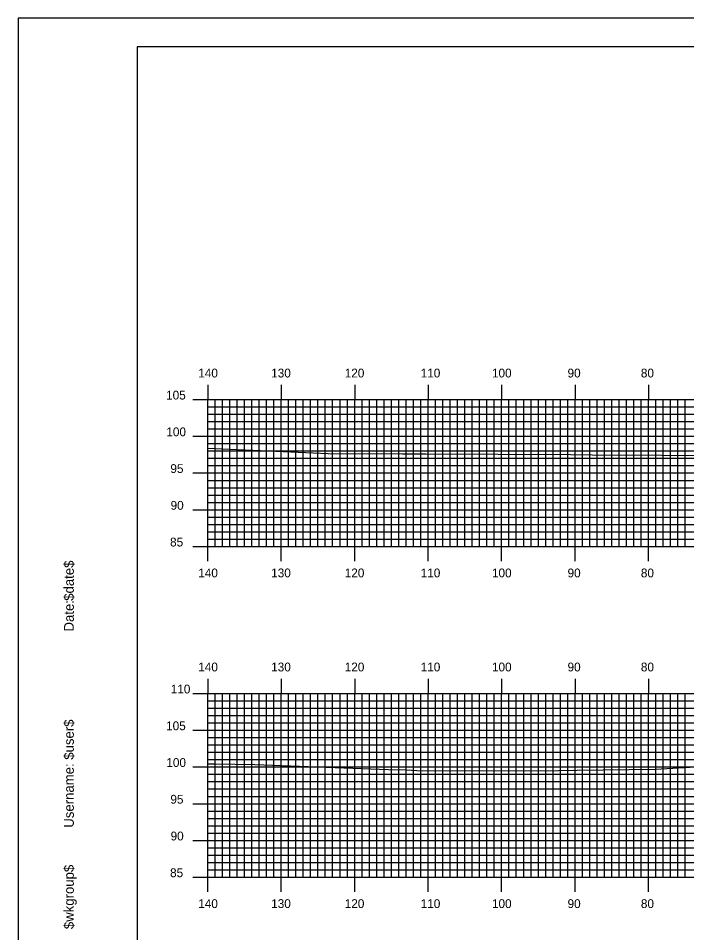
# Model space of a CAD drawing. Extents: x 1775170 to 1775514, y 442591 to 442811.
# Drawn here: x 1775170.4 to 1775261.4, y 442686.1 to 442810.5 of the extents above; entities that cross this region are included whole.
import ezdxf

# ---------------------------------------------------------------- set-up
doc = ezdxf.new("R2010")
doc.units = 0
for name, color, linetype in [('BORDER', 7, 'Continuous'), ('H_V ANNOTATION', 7, 'Continuous'), ('MAJOR', 7, 'Continuous'), ('MINOR', 7, 'Continuous'), ('PLOT BOUNDARY', 7, 'Continuous'), ('S_Roadway_Centerline', 7, 'Continuous')]:
    doc.layers.add(name, color=color, linetype=linetype)

msp = doc.modelspace()

# ---------------------------------------------------------------- linework, layer by layer
at = {"layer": 'BORDER'}
msp.add_lwpolyline([(1775186.6, 442596.67), (1775506.6, 442596.67), (1775506.6, 442806.67), (1775186.6, 442806.67)], close=True, dxfattribs=at)
at = {"layer": 'MAJOR'}
for p, q in [((1775196.2, 442760.67), (1775196.2, 442758.67)), ((1775206.2, 442760.67), (1775206.2, 442758.67)), ((1775216.2, 442760.67), (1775216.2, 442758.67)), ((1775226.2, 442760.67), (1775226.2, 442758.67)), ((1775236.2, 442760.67), (1775236.2, 442758.67)), ((1775246.2, 442760.67), (1775246.2, 442758.67)), ((1775256.2, 442760.67), (1775256.2, 442758.67)), ((1775194.19, 442758.67), (1775196.2, 442758.67)), ((1775196.2, 442758.67), (1775476.2, 442758.67)), ((1775196.2, 442738.67), (1775196.2, 442758.67)), ((1775196.2, 442738.67), (1775196.2, 442758.67)), ((1775196.2, 442758.67), (1775476.2, 442758.67)), ((1775206.2, 442738.67), (1775206.2, 442758.67)), ((1775216.2, 442738.67), (1775216.2, 442758.67)), ((1775226.2, 442738.67), (1775226.2, 442758.67)), ((1775236.2, 442738.67), (1775236.2, 442758.67)), ((1775246.2, 442738.67), (1775246.2, 442758.67)), ((1775256.2, 442738.67), (1775256.2, 442758.67)), ((1775194.19, 442753.67), (1775196.2, 442753.67)), ((1775196.2, 442753.67), (1775476.2, 442753.67)), ((1775194.19, 442748.67), (1775196.2, 442748.67)), ((1775196.2, 442748.67), (1775476.2, 442748.67)), ((1775194.19, 442743.67), (1775196.2, 442743.67)), ((1775196.2, 442743.67), (1775476.2, 442743.67)), ((1775194.19, 442738.67), (1775196.2, 442738.67)), ((1775196.2, 442738.67), (1775476.2, 442738.67)), ((1775196.2, 442738.67), (1775476.2, 442738.67)), ((1775196.2, 442736.66), (1775196.2, 442738.67)), ((1775206.2, 442736.66), (1775206.2, 442738.67)), ((1775216.2, 442736.66), (1775216.2, 442738.67)), ((1775226.2, 442736.66), (1775226.2, 442738.67)), ((1775236.2, 442736.66), (1775236.2, 442738.67)), ((1775246.2, 442736.66), (1775246.2, 442738.67)), ((1775256.2, 442736.66), (1775256.2, 442738.67)), ((1775196.2, 442720.67), (1775196.2, 442718.67)), ((1775206.2, 442720.67), (1775206.2, 442718.67)), ((1775216.2, 442720.67), (1775216.2, 442718.67)), ((1775226.2, 442720.67), (1775226.2, 442718.67)), ((1775236.2, 442720.67), (1775236.2, 442718.67)), ((1775246.2, 442720.67), (1775246.2, 442718.67)), ((1775256.2, 442720.67), (1775256.2, 442718.67)), ((1775194.19, 442718.67), (1775196.2, 442718.67)), ((1775196.2, 442718.67), (1775476.2, 442718.67)), ((1775196.2, 442693.67), (1775196.2, 442718.67)), ((1775196.2, 442693.67), (1775196.2, 442718.67)), ((1775196.2, 442718.67), (1775476.2, 442718.67)), ((1775206.2, 442693.67), (1775206.2, 442718.67)), ((1775216.2, 442693.67), (1775216.2, 442718.67)), ((1775226.2, 442693.67), (1775226.2, 442718.67)), ((1775236.2, 442693.67), (1775236.2, 442718.67)), ((1775246.2, 442693.67), (1775246.2, 442718.67)), ((1775256.2, 442693.67), (1775256.2, 442718.67)), ((1775194.19, 442713.67), (1775196.2, 442713.67)), ((1775196.2, 442713.67), (1775476.2, 442713.67)), ((1775194.19, 442708.67), (1775196.2, 442708.67)), ((1775196.2, 442708.67), (1775476.2, 442708.67)), ((1775194.19, 442703.67), (1775196.2, 442703.67)), ((1775196.2, 442703.67), (1775476.2, 442703.67)), ((1775194.19, 442698.67), (1775196.2, 442698.67)), ((1775196.2, 442698.67), (1775476.2, 442698.67)), ((1775194.19, 442693.67), (1775196.2, 442693.67)), ((1775196.2, 442693.67), (1775476.2, 442693.67)), ((1775196.2, 442693.67), (1775476.2, 442693.67)), ((1775196.2, 442691.66), (1775196.2, 442693.67)), ((1775206.2, 442691.66), (1775206.2, 442693.67)), ((1775216.2, 442691.66), (1775216.2, 442693.67)), ((1775226.2, 442691.66), (1775226.2, 442693.67)), ((1775236.2, 442691.66), (1775236.2, 442693.67)), ((1775246.2, 442691.66), (1775246.2, 442693.67)), ((1775256.2, 442691.66), (1775256.2, 442693.67))]:
    msp.add_line(p, q, dxfattribs=at)
at = {"layer": 'MINOR'}
for p, q in [((1775196.2, 442757.67), (1775476.2, 442757.67)), ((1775196.2, 442757.67), (1775198.2, 442757.67)), ((1775197.2, 442738.67), (1775197.2, 442758.67)), ((1775198.2, 442738.67), (1775198.2, 442758.67)), ((1775199.2, 442738.67), (1775199.2, 442758.67)), ((1775200.2, 442738.67), (1775200.2, 442758.67)), ((1775201.2, 442738.67), (1775201.2, 442758.67)), ((1775202.2, 442738.67), (1775202.2, 442758.67)), ((1775203.2, 442738.67), (1775203.2, 442758.67)), ((1775204.2, 442738.67), (1775204.2, 442758.67)), ((1775205.2, 442738.67), (1775205.2, 442758.67)), ((1775207.2, 442738.67), (1775207.2, 442758.67)), ((1775208.2, 442738.67), (1775208.2, 442758.67)), ((1775209.2, 442738.67), (1775209.2, 442758.67)), ((1775210.2, 442738.67), (1775210.2, 442758.67)), ((1775211.2, 442738.67), (1775211.2, 442758.67)), ((1775212.2, 442738.67), (1775212.2, 442758.67)), ((1775213.2, 442738.67), (1775213.2, 442758.67)), ((1775214.2, 442738.67), (1775214.2, 442758.67)), ((1775215.2, 442738.67), (1775215.2, 442758.67)), ((1775217.2, 442738.67), (1775217.2, 442758.67)), ((1775218.2, 442738.67), (1775218.2, 442758.67)), ((1775219.2, 442738.67), (1775219.2, 442758.67)), ((1775220.2, 442738.67), (1775220.2, 442758.67)), ((1775221.2, 442738.67), (1775221.2, 442758.67)), ((1775222.2, 442738.67), (1775222.2, 442758.67)), ((1775223.2, 442738.67), (1775223.2, 442758.67)), ((1775224.2, 442738.67), (1775224.2, 442758.67)), ((1775225.2, 442738.67), (1775225.2, 442758.67)), ((1775227.2, 442738.67), (1775227.2, 442758.67)), ((1775228.2, 442738.67), (1775228.2, 442758.67)), ((1775229.2, 442738.67), (1775229.2, 442758.67)), ((1775230.2, 442738.67), (1775230.2, 442758.67)), ((1775231.2, 442738.67), (1775231.2, 442758.67)), ((1775232.2, 442738.67), (1775232.2, 442758.67)), ((1775233.2, 442738.67), (1775233.2, 442758.67)), ((1775234.2, 442738.67), (1775234.2, 442758.67)), ((1775235.2, 442738.67), (1775235.2, 442758.67)), ((1775237.2, 442738.67), (1775237.2, 442758.67)), ((1775238.2, 442738.67), (1775238.2, 442758.67)), ((1775239.2, 442738.67), (1775239.2, 442758.67)), ((1775240.2, 442738.67), (1775240.2, 442758.67)), ((1775241.2, 442738.67), (1775241.2, 442758.67)), ((1775242.2, 442738.67), (1775242.2, 442758.67)), ((1775243.2, 442738.67), (1775243.2, 442758.67)), ((1775244.2, 442738.67), (1775244.2, 442758.67)), ((1775245.2, 442738.67), (1775245.2, 442758.67)), ((1775247.2, 442738.67), (1775247.2, 442758.67)), ((1775248.2, 442738.67), (1775248.2, 442758.67)), ((1775249.2, 442738.67), (1775249.2, 442758.67)), ((1775250.2, 442738.67), (1775250.2, 442758.67)), ((1775251.2, 442738.67), (1775251.2, 442758.67)), ((1775252.2, 442738.67), (1775252.2, 442758.67)), ((1775253.2, 442738.67), (1775253.2, 442758.67)), ((1775254.2, 442738.67), (1775254.2, 442758.67)), ((1775255.2, 442738.67), (1775255.2, 442758.67)), ((1775257.2, 442738.67), (1775257.2, 442758.67)), ((1775258.2, 442738.67), (1775258.2, 442758.67)), ((1775259.2, 442738.67), (1775259.2, 442758.67)), ((1775260.2, 442738.67), (1775260.2, 442758.67)), ((1775261.2, 442738.67), (1775261.2, 442758.67)), ((1775196.2, 442756.67), (1775476.2, 442756.67)), ((1775196.2, 442756.67), (1775198.2, 442756.67)), ((1775196.2, 442755.67), (1775476.2, 442755.67)), ((1775196.2, 442755.67), (1775198.2, 442755.67)), ((1775196.2, 442754.67), (1775476.2, 442754.67)), ((1775196.2, 442754.67), (1775198.2, 442754.67)), ((1775196.2, 442752.67), (1775476.2, 442752.67)), ((1775196.2, 442752.67), (1775198.2, 442752.67)), ((1775196.2, 442751.67), (1775476.2, 442751.67)), ((1775196.2, 442751.67), (1775198.2, 442751.67)), ((1775196.2, 442750.67), (1775476.2, 442750.67)), ((1775196.2, 442750.67), (1775198.2, 442750.67)), ((1775196.2, 442749.67), (1775476.2, 442749.67)), ((1775196.2, 442749.67), (1775198.2, 442749.67)), ((1775196.2, 442747.67), (1775476.2, 442747.67)), ((1775196.2, 442747.67), (1775198.2, 442747.67)), ((1775196.2, 442746.67), (1775476.2, 442746.67)), ((1775196.2, 442746.67), (1775198.2, 442746.67)), ((1775196.2, 442745.67), (1775476.2, 442745.67)), ((1775196.2, 442745.67), (1775198.2, 442745.67)), ((1775196.2, 442744.67), (1775476.2, 442744.67)), ((1775196.2, 442744.67), (1775198.2, 442744.67)), ((1775196.2, 442742.67), (1775476.2, 442742.67)), ((1775196.2, 442742.67), (1775198.2, 442742.67)), ((1775196.2, 442741.67), (1775476.2, 442741.67)), ((1775196.2, 442741.67), (1775198.2, 442741.67)), ((1775196.2, 442740.67), (1775476.2, 442740.67)), ((1775196.2, 442740.67), (1775198.2, 442740.67)), ((1775196.2, 442739.67), (1775476.2, 442739.67)), ((1775196.2, 442739.67), (1775198.2, 442739.67)), ((1775197.2, 442693.67), (1775197.2, 442718.67)), ((1775198.2, 442693.67), (1775198.2, 442718.67)), ((1775199.2, 442693.67), (1775199.2, 442718.67)), ((1775200.2, 442693.67), (1775200.2, 442718.67)), ((1775201.2, 442693.67), (1775201.2, 442718.67)), ((1775202.2, 442693.67), (1775202.2, 442718.67)), ((1775203.2, 442693.67), (1775203.2, 442718.67)), ((1775204.2, 442693.67), (1775204.2, 442718.67)), ((1775205.2, 442693.67), (1775205.2, 442718.67)), ((1775207.2, 442693.67), (1775207.2, 442718.67)), ((1775208.2, 442693.67), (1775208.2, 442718.67)), ((1775209.2, 442693.67), (1775209.2, 442718.67)), ((1775210.2, 442693.67), (1775210.2, 442718.67)), ((1775211.2, 442693.67), (1775211.2, 442718.67)), ((1775212.2, 442693.67), (1775212.2, 442718.67)), ((1775213.2, 442693.67), (1775213.2, 442718.67)), ((1775214.2, 442693.67), (1775214.2, 442718.67)), ((1775215.2, 442693.67), (1775215.2, 442718.67)), ((1775217.2, 442693.67), (1775217.2, 442718.67)), ((1775218.2, 442693.67), (1775218.2, 442718.67)), ((1775219.2, 442693.67), (1775219.2, 442718.67)), ((1775220.2, 442693.67), (1775220.2, 442718.67)), ((1775221.2, 442693.67), (1775221.2, 442718.67)), ((1775222.2, 442693.67), (1775222.2, 442718.67)), ((1775223.2, 442693.67), (1775223.2, 442718.67)), ((1775224.2, 442693.67), (1775224.2, 442718.67)), ((1775225.2, 442693.67), (1775225.2, 442718.67)), ((1775227.2, 442693.67), (1775227.2, 442718.67)), ((1775228.2, 442693.67), (1775228.2, 442718.67)), ((1775229.2, 442693.67), (1775229.2, 442718.67)), ((1775230.2, 442693.67), (1775230.2, 442718.67)), ((1775231.2, 442693.67), (1775231.2, 442718.67)), ((1775232.2, 442693.67), (1775232.2, 442718.67)), ((1775233.2, 442693.67), (1775233.2, 442718.67)), ((1775234.2, 442693.67), (1775234.2, 442718.67)), ((1775235.2, 442693.67), (1775235.2, 442718.67)), ((1775237.2, 442693.67), (1775237.2, 442718.67)), ((1775238.2, 442693.67), (1775238.2, 442718.67)), ((1775239.2, 442693.67), (1775239.2, 442718.67)), ((1775240.2, 442693.67), (1775240.2, 442718.67)), ((1775241.2, 442693.67), (1775241.2, 442718.67)), ((1775242.2, 442693.67), (1775242.2, 442718.67)), ((1775243.2, 442693.67), (1775243.2, 442718.67)), ((1775244.2, 442693.67), (1775244.2, 442718.67)), ((1775245.2, 442693.67), (1775245.2, 442718.67)), ((1775247.2, 442693.67), (1775247.2, 442718.67)), ((1775248.2, 442693.67), (1775248.2, 442718.67)), ((1775249.2, 442693.67), (1775249.2, 442718.67)), ((1775250.2, 442693.67), (1775250.2, 442718.67)), ((1775251.2, 442693.67), (1775251.2, 442718.67)), ((1775252.2, 442693.67), (1775252.2, 442718.67)), ((1775253.2, 442693.67), (1775253.2, 442718.67)), ((1775254.2, 442693.67), (1775254.2, 442718.67)), ((1775255.2, 442693.67), (1775255.2, 442718.67)), ((1775257.2, 442693.67), (1775257.2, 442718.67)), ((1775258.2, 442693.67), (1775258.2, 442718.67)), ((1775259.2, 442693.67), (1775259.2, 442718.67)), ((1775260.2, 442693.67), (1775260.2, 442718.67)), ((1775261.2, 442693.67), (1775261.2, 442718.67)), ((1775196.2, 442717.67), (1775476.2, 442717.67)), ((1775196.2, 442717.67), (1775198.2, 442717.67)), ((1775196.2, 442716.67), (1775476.2, 442716.67)), ((1775196.2, 442716.67), (1775198.2, 442716.67)), ((1775196.2, 442715.67), (1775476.2, 442715.67)), ((1775196.2, 442715.67), (1775198.2, 442715.67)), ((1775196.2, 442714.67), (1775476.2, 442714.67)), ((1775196.2, 442714.67), (1775198.2, 442714.67)), ((1775196.2, 442712.67), (1775476.2, 442712.67)), ((1775196.2, 442712.67), (1775198.2, 442712.67)), ((1775196.2, 442711.67), (1775476.2, 442711.67)), ((1775196.2, 442711.67), (1775198.2, 442711.67)), ((1775196.2, 442710.67), (1775476.2, 442710.67)), ((1775196.2, 442710.67), (1775198.2, 442710.67)), ((1775196.2, 442709.67), (1775476.2, 442709.67)), ((1775196.2, 442709.67), (1775198.2, 442709.67)), ((1775196.2, 442707.67), (1775476.2, 442707.67)), ((1775196.2, 442707.67), (1775198.2, 442707.67)), ((1775196.2, 442706.67), (1775476.2, 442706.67)), ((1775196.2, 442706.67), (1775198.2, 442706.67)), ((1775196.2, 442705.67), (1775476.2, 442705.67)), ((1775196.2, 442705.67), (1775198.2, 442705.67)), ((1775196.2, 442704.67), (1775476.2, 442704.67)), ((1775196.2, 442704.67), (1775198.2, 442704.67)), ((1775196.2, 442702.67), (1775476.2, 442702.67)), ((1775196.2, 442702.67), (1775198.2, 442702.67)), ((1775196.2, 442701.67), (1775476.2, 442701.67)), ((1775196.2, 442701.67), (1775198.2, 442701.67)), ((1775196.2, 442700.67), (1775476.2, 442700.67)), ((1775196.2, 442700.67), (1775198.2, 442700.67)), ((1775196.2, 442699.67), (1775476.2, 442699.67)), ((1775196.2, 442699.67), (1775198.2, 442699.67)), ((1775196.2, 442697.67), (1775476.2, 442697.67)), ((1775196.2, 442697.67), (1775198.2, 442697.67)), ((1775196.2, 442696.67), (1775476.2, 442696.67)), ((1775196.2, 442696.67), (1775198.2, 442696.67)), ((1775196.2, 442695.67), (1775476.2, 442695.67)), ((1775196.2, 442695.67), (1775198.2, 442695.67)), ((1775196.2, 442694.67), (1775476.2, 442694.67)), ((1775196.2, 442694.67), (1775198.2, 442694.67))]:
    msp.add_line(p, q, dxfattribs=at)
at = {"layer": 'PLOT BOUNDARY'}
msp.add_lwpolyline([(1775170.41, 442590.55), (1775510.41, 442590.55), (1775510.41, 442810.55), (1775170.41, 442810.55)], close=True, dxfattribs=at)
at = {"layer": 'S_Roadway_Centerline'}
for points in [[(1775196.2, 442752.05), (1775199.14, 442751.93), (1775202.38, 442751.79), (1775212.6, 442751.34), (1775222.71, 442751.28), (1775225.88, 442751.29), (1775245.56, 442751.18), (1775248.52, 442751.12), (1775267.46, 442751.03)], [(1775196.2, 442709.09), (1775197.2, 442709.1), (1775202.6, 442709.02), (1775220.78, 442708.3), (1775223.18, 442708.28), (1775225.44, 442708.15), (1775243.95, 442708.19), (1775246.5, 442708.25), (1775257.1, 442708.39), (1775268.25, 442709.02)]]:
    msp.add_lwpolyline(points, dxfattribs=at)

# ---------------------------------------------------------------- texts
at = {"layer": 'BORDER'}
for s, p in [('$date$', (1775177.97, 442731.28)), ('Date:', (1775177.97, 442727.1)), ('$user$', (1775177.97, 442709.65)), ('Username:', (1775177.97, 442700.4)), ('$wkgroup$', (1775177.97, 442686.6))]:
    msp.add_text(s, height=1.339, rotation=90, dxfattribs=at).set_placement(p)
at = {"layer": 'H_V ANNOTATION'}
for s, p in [('140', (1775194.9, 442761.67)), ('130', (1775204.83, 442761.67)), ('120', (1775214.84, 442761.67)), ('110', (1775225.18, 442761.67)), ('100', (1775234.88, 442761.67)), ('90', (1775245.17, 442761.67)), ('80', (1775255.15, 442761.67)), ('105', (1775190.53, 442758.67)), ('100', (1775190.56, 442753.67)), ('95', (1775191.11, 442748.67)), ('90', (1775191.14, 442743.67)), ('85', (1775191.07, 442738.67)), ('140', (1775194.9, 442734.47)), ('130', (1775204.83, 442734.47)), ('120', (1775214.84, 442734.47)), ('110', (1775225.18, 442734.47)), ('100', (1775234.88, 442734.47)), ('90', (1775245.17, 442734.47)), ('80', (1775255.15, 442734.47)), ('140', (1775194.9, 442721.67)), ('130', (1775204.83, 442721.67)), ('120', (1775214.84, 442721.67)), ('110', (1775225.18, 442721.67)), ('100', (1775234.88, 442721.67)), ('90', (1775245.17, 442721.67)), ('80', (1775255.15, 442721.67)), ('110', (1775191.16, 442718.67)), ('105', (1775190.53, 442713.67)), ('100', (1775190.56, 442708.67)), ('95', (1775191.11, 442703.67)), ('90', (1775191.14, 442698.67)), ('85', (1775191.07, 442693.67)), ('140', (1775194.9, 442689.47)), ('130', (1775204.83, 442689.47)), ('120', (1775214.84, 442689.47)), ('110', (1775225.18, 442689.47)), ('100', (1775234.88, 442689.47)), ('90', (1775245.17, 442689.47)), ('80', (1775255.15, 442689.47))]:
    msp.add_text(s, height=1.2, dxfattribs=at).set_placement(p)
at = {"layer": 'MAJOR'}
for p in [(1775196.19, 442738.67), (1775196.19, 442693.67)]:
    msp.add_text('-', height=0.012, dxfattribs=at).set_placement(p)

doc.saveas('drawing.dxf')
